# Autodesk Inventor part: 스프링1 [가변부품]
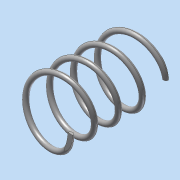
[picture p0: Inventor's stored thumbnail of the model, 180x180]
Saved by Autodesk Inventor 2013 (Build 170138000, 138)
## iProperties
Created: 2015-08
Part Number: 스프링1 [가변부품]
Material: 강철, 연강
Document SubType Name: Modeling
Designer: dgall
Density: 7.86 g/cm^3
Mass: 2.84502 g
Surface Area: 9.78731 cm^2
Volume: 0.361961 cm^3
Author: dgall
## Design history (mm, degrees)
sketch "스케치1"
  geometry: L1 (0, 0)-(8.25, 0); L2 (8.25, 0)-(8.25, 28); L3 (8.25, 28)-(0, 28); L4 (0, 28)-(0, 0); C1 r 0.75 at (8.25, 0)
  constraints: 8 end point, 2 parallel, 1 centre point, 1 coincident, 1 horizontal, 1 perpendicular
  dimensions: "d0" = 8.25 distance of L2.end L3.end; "d2" = 28 distance of L1.end L2.end (derived); "d3" = 1.5 diameter of C1
feature "코일1" sketch "스케치1" pitch "d4" = 10; turns "d6" = 4; dims "d5" = 28 (= d2), "d7" = 0, angle "d8" = 90 deg, angle "d9" = 90 deg, "d10" = 0, "d11" = 0
sketch "스케치2"
  geometry: L1 (-14.532, 13.337)-(25.43, 13.337); L2 (25.43, 13.337)-(25.43, -20.793); L3 (25.43, -20.793)-(-14.532, -20.793); L4 (-14.532, -20.793)-(-14.532, 13.337); 1 further point
  constraints: 8 end point, 2 parallel, 1 horizontal, 1 perpendicular
extrude "돌출1" cut sketch "스케치2" distance "d12" = 10; taper "d13" = 0 deg
node "작업 평면1"
sketch "스케치3"
  geometry: L1 (-10.503, 17.639)-(25.73, 17.639); L2 (25.73, 17.639)-(25.73, -19.168); L3 (25.73, -19.168)-(-10.503, -19.168); L4 (-10.503, -19.168)-(-10.503, 17.639); 1 further point
  constraints: 8 end point, 2 parallel, 1 horizontal, 1 perpendicular
extrude "돌출2" cut sketch "스케치3" distance "d14" = 10; taper "d15" = 0 deg
node "솔리드1"
